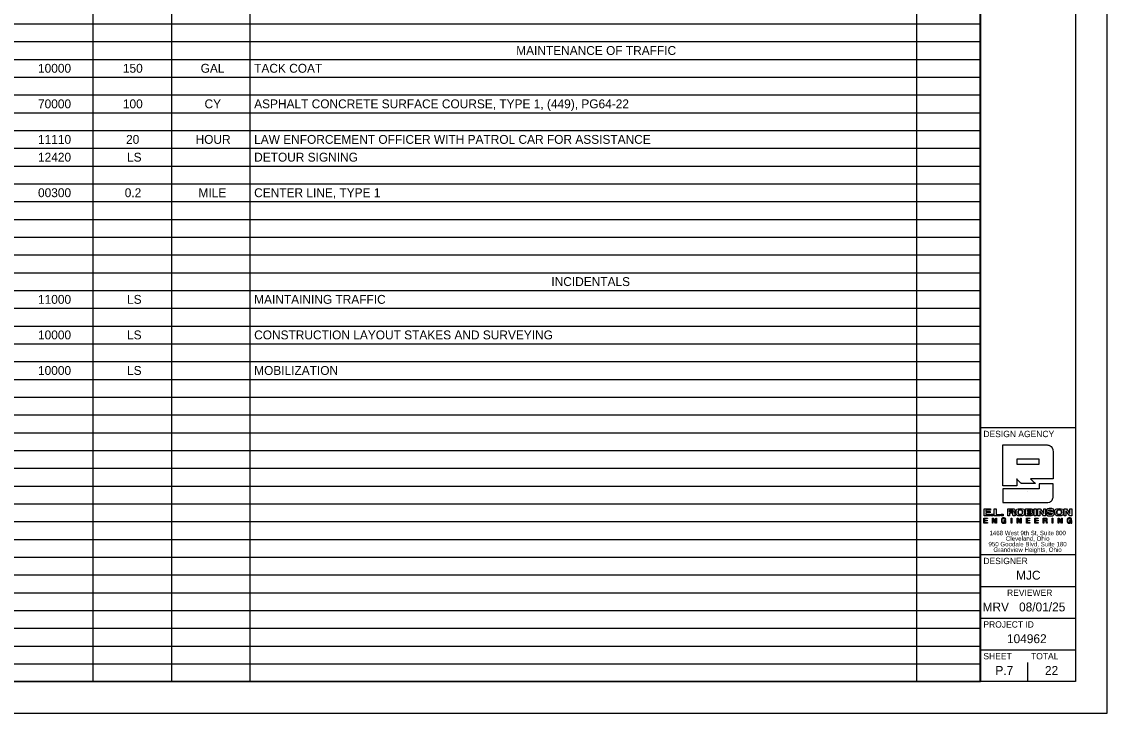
# Model space of a CAD drawing. Extents: x 0 to 34, y 0 to 22.
# Drawn here: x 16.91 to 34, y 0 to 10.89 of the extents above; entities that cross this region are included whole.
import ezdxf

# ---------------------------------------------------------------- set-up
doc = ezdxf.new("R2010")
doc.units = 0
for name, color, linetype in [('Default', 7, 'Continuous'), ('SH_Border', 7, 'Continuous'), ('SH_Cut_Line', 7, 'Continuous'), ('SH_Data', 7, 'Continuous')]:
    doc.layers.add(name, color=color, linetype=linetype)

msp = doc.modelspace()

# ---------------------------------------------------------------- linework, layer by layer
at = {"layer": 'SH_Border'}
for p, q in [((32, 0.5), (32, 21.5)), ((32, 4.5), (33.5, 4.5)), ((32, 2.5), (33.5, 2.5)), ((32, 2), (33.5, 2)), ((32, 1.5), (33.5, 1.5)), ((32, 1), (33.5, 1))]:
    msp.add_line(p, q, dxfattribs=at)
msp.add_lwpolyline([(1.5, 21.5), (33.5, 21.5), (33.5, 0.5), (1.5, 0.5)], close=True, dxfattribs=at)
at = {"layer": 'SH_Cut_Line'}
msp.add_lwpolyline([(0, 0), (34, 0), (34, 22), (0, 22)], close=True, dxfattribs=at)
at = {"layer": 'SH_Data'}
for p, q in [((18.036, 21.5), (18.036, 0.5)), ((19.272, 21.5), (19.272, 0.5)), ((20.507, 21.5), (20.507, 0.5)), ((30.999, 21.5), (30.999, 0.5)), ((32.004, 21.5), (32.004, 0.5)), ((1.5, 10.86), (32.004, 10.86)), ((1.5, 10.58), (32.004, 10.58)), ((1.5, 10.3), (32.004, 10.3)), ((1.5, 10.02), (32.004, 10.02)), ((1.5, 9.74), (32.004, 9.74)), ((1.5, 9.46), (32.004, 9.46)), ((1.5, 9.18), (32.004, 9.18)), ((1.5, 8.9), (32.004, 8.9)), ((1.5, 8.62), (32.004, 8.62)), ((1.5, 8.34), (32.004, 8.34)), ((1.5, 8.06), (32.004, 8.06)), ((1.5, 7.78), (32.004, 7.78)), ((1.5, 7.5), (32.004, 7.5)), ((1.5, 7.22), (32.004, 7.22)), ((1.5, 6.94), (32.004, 6.94)), ((1.5, 6.66), (32.004, 6.66)), ((1.5, 6.38), (32.004, 6.38)), ((1.5, 6.1), (32.004, 6.1)), ((1.5, 5.82), (32.004, 5.82)), ((1.5, 5.54), (32.004, 5.54)), ((1.5, 5.26), (32.004, 5.26)), ((1.5, 4.98), (32.004, 4.98)), ((1.5, 4.7), (32.004, 4.7)), ((1.5, 4.42), (32.004, 4.42)), ((1.5, 4.14), (32.004, 4.14)), ((32.929, 4.003), (32.574, 4.003)), ((32.574, 4.003), (32.574, 3.925)), ((32.929, 3.925), (32.929, 4.003)), ((1.5, 3.86), (32.004, 3.86)), ((32.574, 3.925), (32.929, 3.925)), ((1.5, 3.58), (32.004, 3.58)), ((32.75, 3.5), (32.75, 3.5)), ((1.5, 3.3), (32.004, 3.3)), ((32.463, 3.201), (32.463, 3.173)), ((32.743, 3.202), (32.743, 3.178)), ((32.743, 3.159), (32.743, 3.133)), ((1.5, 3.02), (32.004, 3.02)), ((33.001, 3.066), (33.001, 3.039)), ((33.001, 3.039), (33.023, 3.039)), ((1.5, 2.74), (32.004, 2.74)), ((1.5, 2.46), (32.004, 2.46)), ((1.5, 2.18), (32.004, 2.18)), ((1.5, 1.9), (32.004, 1.9)), ((1.5, 1.62), (32.004, 1.62)), ((1.5, 1.34), (32.004, 1.34)), ((1.5, 1.06), (32.004, 1.06)), ((1.5, 0.78), (32.004, 0.78)), ((32.75, 0.5), (32.75, 0.8)), ((32.375, 0.675), (32.375, 0.675)), ((1.5, 0.5), (32.004, 0.5))]:
    msp.add_line(p, q, dxfattribs=at)
for points in [[(32.06, 3.221), (32.161, 3.221), (32.161, 3.201), (32.089, 3.201), (32.089, 3.178), (32.158, 3.178), (32.158, 3.158), (32.089, 3.158), (32.089, 3.133), (32.162, 3.133), (32.162, 3.113), (32.06, 3.113), (32.06, 3.221)], [(32.175, 3.139), (32.205, 3.139), (32.205, 3.113), (32.175, 3.113), (32.175, 3.139)], [(32.22, 3.221), (32.249, 3.221), (32.249, 3.134), (32.316, 3.134), (32.316, 3.113), (32.22, 3.113), (32.22, 3.221)], [(32.331, 3.139), (32.361, 3.139), (32.361, 3.113), (32.331, 3.113), (32.331, 3.139)], [(32.851, 3.221), (32.881, 3.221), (32.881, 3.113), (32.851, 3.113), (32.851, 3.221)], [(32.999, 3.221), (33.027, 3.221), (33.027, 3.113), (32.995, 3.113), (32.936, 3.189), (32.936, 3.189), (32.936, 3.113), (32.907, 3.113), (32.907, 3.221), (32.941, 3.221), (32.999, 3.146), (32.999, 3.146), (32.999, 3.221)], [(33.413, 3.221), (33.442, 3.221), (33.442, 3.113), (33.41, 3.113), (33.35, 3.189), (33.35, 3.189), (33.35, 3.113), (33.321, 3.113), (33.321, 3.221), (33.356, 3.221), (33.413, 3.146), (33.413, 3.146), (33.413, 3.221)], [(32.059, 3.075), (32.114, 3.075), (32.114, 3.066), (32.07, 3.066), (32.07, 3.041), (32.111, 3.041), (32.111, 3.032), (32.07, 3.032), (32.07, 3.005), (32.114, 3.005), (32.114, 2.996), (32.059, 2.996), (32.059, 3.075)], [(32.191, 3.075), (32.203, 3.075), (32.244, 3.011), (32.244, 3.011), (32.244, 3.075), (32.254, 3.075), (32.254, 2.996), (32.243, 2.996), (32.202, 3.059), (32.201, 3.059), (32.201, 2.996), (32.191, 2.996), (32.191, 3.075)], [(32.487, 3.075), (32.498, 3.075), (32.498, 2.996), (32.487, 2.996), (32.487, 3.075)], [(32.581, 3.075), (32.592, 3.075), (32.633, 3.011), (32.633, 3.011), (32.633, 3.075), (32.643, 3.075), (32.643, 2.996), (32.632, 2.996), (32.591, 3.059), (32.591, 3.059), (32.591, 2.996), (32.581, 2.996), (32.581, 3.075)], [(32.726, 3.075), (32.781, 3.075), (32.781, 3.066), (32.737, 3.066), (32.737, 3.041), (32.778, 3.041), (32.778, 3.032), (32.737, 3.032), (32.737, 3.005), (32.781, 3.005), (32.781, 2.996), (32.726, 2.996), (32.726, 3.075)], [(32.859, 3.075), (32.913, 3.075), (32.913, 3.066), (32.869, 3.066), (32.869, 3.041), (32.91, 3.041), (32.91, 3.032), (32.869, 3.032), (32.869, 3.005), (32.913, 3.005), (32.913, 2.996), (32.859, 2.996), (32.859, 3.075)], [(33.133, 3.075), (33.143, 3.075), (33.143, 2.996), (33.133, 2.996), (33.133, 3.075)], [(33.226, 3.075), (33.237, 3.075), (33.279, 3.011), (33.279, 3.011), (33.279, 3.075), (33.289, 3.075), (33.289, 2.996), (33.277, 2.996), (33.236, 3.059), (33.236, 3.059), (33.236, 2.996), (33.226, 2.996), (33.226, 3.075)]]:
    msp.add_lwpolyline(points, dxfattribs=at)
for points, degree in [([(32.356, 3.583), (32.356, 3.586), (32.356, 4.224), (32.356, 4.227)], 2), ([(32.356, 4.227), (32.36, 4.227), (33.03, 4.227), (33.034, 4.227), (33.096, 4.227), (33.147, 4.177), (33.147, 4.114)], 3), ([(33.147, 4.114), (33.147, 4.112), (33.147, 3.694), (33.147, 3.692)], 2), ([(32.929, 3.615), (32.929, 3.615), (33.147, 3.615), (33.147, 3.615), (33.147, 3.615), (33.147, 3.433), (33.147, 3.433), (33.147, 3.37), (33.096, 3.32), (33.034, 3.32), (33.034, 3.32), (32.356, 3.32), (32.356, 3.32), (32.356, 3.32), (32.356, 3.537), (32.356, 3.537), (32.356, 3.537), (32.929, 3.537), (32.929, 3.537), (32.929, 3.537), (32.929, 3.615), (32.929, 3.615)], 3), ([(32.645, 3.621), (32.645, 3.621), (32.574, 3.691), (32.574, 3.692)], 2), ([(32.574, 3.692), (32.574, 3.691), (32.574, 3.583), (32.574, 3.583)], 2), ([(32.866, 3.621), (32.865, 3.621), (32.646, 3.621), (32.645, 3.621)], 2), ([(33.147, 3.692), (33.145, 3.692), (32.795, 3.692), (32.793, 3.692)], 2), ([(32.793, 3.692), (32.793, 3.691), (32.866, 3.621), (32.866, 3.621)], 2), ([(32.574, 3.583), (32.573, 3.583), (32.357, 3.583), (32.356, 3.583)], 2), ([(32.396, 3.006), (32.39, 2.998), (32.38, 2.994), (32.37, 2.994), (32.347, 2.994), (32.333, 3.014), (32.333, 3.034), (32.333, 3.057), (32.346, 3.077), (32.37, 3.077), (32.388, 3.077), (32.401, 3.069), (32.404, 3.051), (32.404, 3.051), (32.394, 3.051), (32.394, 3.051), (32.392, 3.062), (32.382, 3.068), (32.37, 3.068), (32.351, 3.068), (32.344, 3.051), (32.344, 3.034), (32.344, 3.018), (32.353, 3.003), (32.37, 3.003), (32.387, 3.003), (32.396, 3.015), (32.396, 3.029), (32.396, 3.029), (32.371, 3.029), (32.371, 3.029), (32.371, 3.029), (32.371, 3.038), (32.371, 3.038), (32.371, 3.038), (32.405, 3.038), (32.405, 3.038), (32.405, 3.038), (32.405, 2.996), (32.405, 2.996), (32.405, 2.996), (32.398, 2.996), (32.398, 2.996), (32.398, 2.996), (32.396, 3.006), (32.396, 3.006)], 3), ([(32.433, 3.113), (32.433, 3.113), (32.433, 3.221), (32.433, 3.221)], 2), ([(32.433, 3.221), (32.433, 3.221), (32.512, 3.221), (32.512, 3.221), (32.542, 3.221), (32.545, 3.203), (32.546, 3.192)], 3), ([(32.463, 3.113), (32.462, 3.113), (32.433, 3.113), (32.433, 3.113)], 2), ([(32.499, 3.153), (32.499, 3.153), (32.463, 3.153), (32.463, 3.153)], 2), ([(32.463, 3.173), (32.463, 3.173), (32.502, 3.173), (32.502, 3.173), (32.508, 3.173), (32.516, 3.177), (32.516, 3.187), (32.516, 3.198), (32.507, 3.201), (32.5, 3.201), (32.5, 3.201), (32.463, 3.201), (32.463, 3.201), (32.463, 3.201), (32.463, 3.173), (32.463, 3.173)], 3), ([(32.463, 3.173), (32.476, 3.173), (32.489, 3.173), (32.508, 3.173), (32.516, 3.177), (32.516, 3.198), (32.507, 3.201), (32.488, 3.201), (32.475, 3.201), (32.463, 3.201)], 3), ([(32.463, 3.153), (32.463, 3.152), (32.463, 3.113), (32.463, 3.113)], 2), ([(32.518, 3.113), (32.516, 3.118), (32.516, 3.122), (32.516, 3.134), (32.515, 3.149), (32.508, 3.15), (32.499, 3.153)], 3), ([(32.55, 3.113), (32.55, 3.113), (32.518, 3.113), (32.518, 3.113)], 2), ([(32.546, 3.192), (32.544, 3.179), (32.542, 3.17), (32.53, 3.166)], 2), ([(32.53, 3.166), (32.53, 3.166), (32.53, 3.165), (32.53, 3.165)], 2), ([(32.53, 3.165), (32.543, 3.163), (32.544, 3.147), (32.544, 3.136)], 2), ([(32.544, 3.136), (32.544, 3.131), (32.548, 3.119), (32.55, 3.113)], 2), ([(32.631, 3.11), (32.573, 3.11), (32.567, 3.145), (32.565, 3.167), (32.564, 3.19), (32.573, 3.224), (32.631, 3.224)], 3), ([(32.631, 3.13), (32.658, 3.13), (32.667, 3.15), (32.667, 3.167), (32.667, 3.184), (32.658, 3.204), (32.631, 3.204), (32.604, 3.204), (32.595, 3.184), (32.595, 3.167), (32.595, 3.15), (32.604, 3.13), (32.631, 3.13)], 3), ([(32.631, 3.204), (32.604, 3.204), (32.595, 3.184), (32.595, 3.167), (32.595, 3.15), (32.604, 3.13), (32.631, 3.13)], 3), ([(32.631, 3.224), (32.69, 3.224), (32.695, 3.189), (32.697, 3.167), (32.699, 3.144), (32.69, 3.11), (32.631, 3.11)], 3), ([(32.631, 3.13), (32.658, 3.13), (32.667, 3.15), (32.667, 3.167), (32.667, 3.184), (32.658, 3.204), (32.631, 3.204)], 3), ([(32.714, 3.113), (32.714, 3.113), (32.714, 3.221), (32.714, 3.221)], 2), ([(32.714, 3.221), (32.714, 3.221), (32.795, 3.221), (32.795, 3.221)], 2), ([(32.829, 3.145), (32.827, 3.132), (32.824, 3.113), (32.791, 3.113), (32.791, 3.113), (32.714, 3.113), (32.714, 3.113)], 3), ([(32.743, 3.178), (32.743, 3.178), (32.784, 3.178), (32.784, 3.178), (32.791, 3.178), (32.796, 3.182), (32.796, 3.19), (32.796, 3.197), (32.793, 3.202), (32.78, 3.202), (32.78, 3.202), (32.743, 3.202), (32.743, 3.202), (32.743, 3.202), (32.743, 3.178), (32.743, 3.178)], 3), ([(32.743, 3.178), (32.757, 3.178), (32.771, 3.178), (32.791, 3.181), (32.791, 3.183), (32.792, 3.197), (32.793, 3.202), (32.768, 3.202), (32.756, 3.202), (32.743, 3.202)], 3), ([(32.743, 3.133), (32.743, 3.133), (32.787, 3.133), (32.787, 3.133), (32.796, 3.133), (32.8, 3.139), (32.8, 3.146), (32.8, 3.155), (32.794, 3.159), (32.784, 3.159), (32.784, 3.159), (32.743, 3.159), (32.743, 3.159), (32.743, 3.159), (32.743, 3.133), (32.743, 3.133)], 3), ([(32.743, 3.133), (32.758, 3.133), (32.772, 3.133), (32.796, 3.133), (32.8, 3.139), (32.8, 3.155), (32.794, 3.159), (32.77, 3.159), (32.757, 3.159), (32.743, 3.159)], 3), ([(32.795, 3.221), (32.81, 3.218), (32.826, 3.214), (32.826, 3.194)], 2), ([(32.826, 3.194), (32.824, 3.186), (32.822, 3.175), (32.812, 3.172)], 2), ([(32.812, 3.172), (32.812, 3.172), (32.812, 3.172), (32.812, 3.172)], 2), ([(32.812, 3.172), (32.824, 3.17), (32.827, 3.156), (32.829, 3.145)], 2), ([(33.126, 3.19), (33.124, 3.204), (33.111, 3.206), (33.099, 3.206), (33.087, 3.206), (33.079, 3.2), (33.079, 3.193), (33.079, 3.187), (33.084, 3.184), (33.091, 3.183), (33.091, 3.183), (33.128, 3.177), (33.128, 3.177), (33.148, 3.173), (33.163, 3.166), (33.163, 3.146), (33.163, 3.126), (33.149, 3.11), (33.107, 3.11), (33.08, 3.11), (33.046, 3.113), (33.045, 3.147), (33.045, 3.147), (33.079, 3.147), (33.079, 3.147), (33.079, 3.132), (33.094, 3.129), (33.107, 3.129), (33.121, 3.129), (33.13, 3.134), (33.13, 3.143), (33.13, 3.151), (33.123, 3.154), (33.112, 3.155), (33.112, 3.155), (33.085, 3.16), (33.085, 3.16), (33.066, 3.162), (33.047, 3.168), (33.047, 3.19), (33.047, 3.215), (33.067, 3.224), (33.101, 3.224), (33.124, 3.224), (33.157, 3.221), (33.159, 3.19), (33.159, 3.19), (33.126, 3.19), (33.126, 3.19)], 3), ([(33.242, 3.11), (33.183, 3.11), (33.178, 3.145), (33.176, 3.167), (33.174, 3.19), (33.183, 3.224), (33.242, 3.224)], 3), ([(33.242, 3.13), (33.269, 3.13), (33.278, 3.15), (33.278, 3.167), (33.278, 3.184), (33.269, 3.204), (33.242, 3.204), (33.215, 3.204), (33.205, 3.184), (33.205, 3.167), (33.205, 3.15), (33.215, 3.13), (33.242, 3.13)], 3), ([(33.242, 3.204), (33.215, 3.204), (33.205, 3.184), (33.205, 3.167), (33.205, 3.15), (33.215, 3.13), (33.242, 3.13)], 3), ([(33.242, 3.224), (33.3, 3.224), (33.306, 3.189), (33.308, 3.167), (33.309, 3.144), (33.3, 3.11), (33.242, 3.11)], 3), ([(33.242, 3.13), (33.269, 3.13), (33.278, 3.15), (33.278, 3.167), (33.278, 3.184), (33.269, 3.204), (33.242, 3.204)], 3), ([(33.43, 3.006), (33.424, 2.998), (33.414, 2.994), (33.405, 2.994), (33.382, 2.994), (33.368, 3.014), (33.368, 3.034), (33.368, 3.057), (33.38, 3.077), (33.405, 3.077), (33.422, 3.077), (33.436, 3.069), (33.439, 3.051), (33.439, 3.051), (33.429, 3.051), (33.429, 3.051), (33.426, 3.062), (33.417, 3.068), (33.405, 3.068), (33.386, 3.068), (33.378, 3.051), (33.378, 3.034), (33.378, 3.018), (33.388, 3.003), (33.405, 3.003), (33.421, 3.003), (33.431, 3.015), (33.43, 3.029), (33.43, 3.029), (33.405, 3.029), (33.405, 3.029), (33.405, 3.029), (33.405, 3.038), (33.405, 3.038), (33.405, 3.038), (33.44, 3.038), (33.44, 3.038), (33.44, 3.038), (33.44, 2.996), (33.44, 2.996), (33.44, 2.996), (33.433, 2.996), (33.433, 2.996), (33.433, 2.996), (33.43, 3.006), (33.43, 3.006)], 3), ([(32.991, 3.075), (32.991, 3.075), (33.027, 3.075), (33.028, 3.075), (33.042, 3.075), (33.051, 3.067), (33.051, 3.054)], 3), ([(32.991, 2.996), (32.991, 2.997), (32.991, 3.074), (32.991, 3.075)], 2), ([(33.001, 2.996), (33.001, 2.996), (32.991, 2.996), (32.991, 2.996)], 2), ([(33.023, 3.039), (33.033, 3.039), (33.041, 3.041), (33.041, 3.052), (33.041, 3.06), (33.037, 3.066), (33.027, 3.066), (33.027, 3.066), (33.001, 3.066), (33.001, 3.066), (33.001, 3.066), (33.001, 3.039), (33.001, 3.039), (33.001, 3.039), (33.023, 3.039), (33.023, 3.039)], 3), ([(33.023, 3.039), (33.033, 3.039), (33.041, 3.041), (33.041, 3.06), (33.037, 3.066), (33.018, 3.066), (33.01, 3.066), (33.001, 3.066)], 3), ([(33.04, 3.016), (33.038, 3.023), (33.037, 3.03), (33.027, 3.03), (33.027, 3.03), (33.001, 3.03), (33.001, 3.03)], 3), ([(33.001, 3.03), (33.001, 3.03), (33.001, 2.996), (33.001, 2.996)], 2), ([(33.051, 3.054), (33.049, 3.045), (33.047, 3.037), (33.038, 3.034)], 2), ([(33.038, 3.034), (33.038, 3.034), (33.038, 3.034), (33.038, 3.034)], 2), ([(33.038, 3.034), (33.044, 3.029), (33.047, 3.025), (33.048, 3.018)], 2), ([(33.043, 2.996), (33.042, 3), (33.041, 3.008), (33.04, 3.016)], 2), ([(33.054, 2.996), (33.054, 2.996), (33.043, 2.996), (33.043, 2.996)], 2), ([(33.048, 3.018), (33.049, 3.01), (33.052, 3.002), (33.054, 2.996)], 2)]:
    msp.add_open_spline(points, degree=degree, dxfattribs=at)

# ---------------------------------------------------------------- texts
at = {"layer": 'Default'}
for s, p in [('MAINTENANCE OF TRAFFIC', (24.697, 10.37)), ('10000', (17.171, 10.09)), ('150', (18.507, 10.09)), ('GAL', (19.731, 10.09)), ('TACK COAT', (20.573, 10.09)), ('70000', (17.171, 9.53)), ('100', (18.507, 9.53)), ('CY', (19.792, 9.53)), ('ASPHALT CONCRETE SURFACE COURSE, TYPE 1, (449), PG64-22', (20.573, 9.53)), ('11110', (17.171, 8.97)), ('20', (18.557, 8.97)), ('HOUR', (19.651, 8.97)), ('LAW ENFORCEMENT OFFICER WITH PATROL CAR FOR ASSISTANCE', (20.573, 8.97)), ('12420', (17.171, 8.69)), ('LS', (18.572, 8.69)), ('DETOUR SIGNING', (20.573, 8.69)), ('00300', (17.171, 8.13)), ('0.2', (18.536, 8.13)), ('MILE', (19.697, 8.13)), ('CENTER LINE, TYPE 1', (20.573, 8.13)), ('INCIDENTALS', (25.251, 6.73)), ('11000', (17.171, 6.45)), ('LS', (18.572, 6.45)), ('MAINTAINING TRAFFIC', (20.573, 6.45)), ('10000', (17.171, 5.89)), ('LS', (18.572, 5.89)), ('CONSTRUCTION LAYOUT STAKES AND SURVEYING', (20.573, 5.89)), ('10000', (17.171, 5.33)), ('LS', (18.572, 5.33)), ('MOBILIZATION', (20.573, 5.33))]:
    msp.add_text(s, height=0.14, dxfattribs=at).set_placement(p)
at = {"layer": 'SH_Data'}
for s, height, p in [('DESIGN AGENCY', 0.1, (32.05, 4.35)), ('1468 West 9th St, Suite 800', 0.07, (32.145, 2.805)), ('Cleveland, Ohio', 0.07, (32.404, 2.717)), ('950 Goodale Blvd, Suite 180', 0.07, (32.13, 2.63)), ('Grandview Heights, Ohio', 0.07, (32.208, 2.542)), ('DESIGNER', 0.1, (32.05, 2.35)), ('MJC', 0.14, (32.565, 2.105)), ('REVIEWER', 0.1, (32.422, 1.85)), ('MRV', 0.14, (32.037, 1.605)), ('08/01/25', 0.14, (32.611, 1.605)), ('PROJECT ID', 0.1, (32.05, 1.35)), ('104962', 0.14, (32.421, 1.105)), ('SHEET', 0.1, (32.05, 0.85)), ('TOTAL', 0.1, (32.8, 0.85)), ('P.7', 0.14, (32.239, 0.605)), ('22', 0.14, (33.019, 0.605))]:
    msp.add_text(s, height=height, dxfattribs=at).set_placement(p)

doc.saveas('drawing.dxf')
